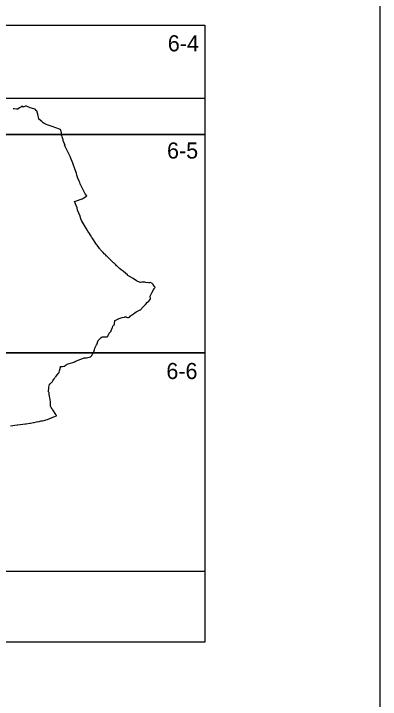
# Model space of a CAD drawing. Extents: x -449577 to -425530, y -1150048 to -1121091.
# Drawn here: x -443133.6 to -442923.9, y -1126663.9 to -1126271.9 of the extents above; entities that cross this region are included whole.
import ezdxf

# ---------------------------------------------------------------- set-up
doc = ezdxf.new("R2010")
doc.units = 0
for name, color, linetype in [('Vrstva 1', 7, 'Continuous'), ('Vrstva 10', 7, 'Continuous'), ('Vrstva 4', 7, 'Continuous')]:
    doc.layers.add(name, color=color, linetype=linetype)

msp = doc.modelspace()

# ---------------------------------------------------------------- linework, layer by layer
at = {"layer": 'Vrstva 1'}
msp.add_lwpolyline([(-444408.89, -1126016.81), (-444408.89, -1127066.81), (-442923.89, -1127066.81), (-442923.89, -1126016.81)], close=True, dxfattribs=at)
msp.add_lwpolyline([(-443135.43, -1126507.56), (-443131.56, -1126506.99), (-443131.32, -1126506.96), (-443127.02, -1126506.44), (-443126.49, -1126506.38), (-443124.34, -1126506.02), (-443124.02, -1126505.97), (-443122.36, -1126505.7), (-443121.96, -1126505.63), (-443120.55, -1126505.34), (-443119.26, -1126505.07), (-443119.05, -1126505.03), (-443117.88, -1126504.8), (-443117.21, -1126504.67), (-443117.19, -1126504.67), (-443116.28, -1126504.46), (-443116.21, -1126504.44), (-443115.56, -1126504.28), (-443115.21, -1126504.17), (-443114.32, -1126503.88), (-443113.88, -1126503.73), (-443113.23, -1126503.49), (-443113.11, -1126503.45), (-443112.02, -1126502.96), (-443112.02, -1126502.96), (-443111.9, -1126502.92), (-443111.25, -1126502.69), (-443111.16, -1126502.66), (-443110.73, -1126502.5), (-443109.07, -1126501.92), (-443109.09, -1126501.87), (-443109.2, -1126501.7), (-443109.36, -1126501.47), (-443109.58, -1126501.15), (-443111.28, -1126498.51), (-443111.49, -1126498.16), (-443111.66, -1126497.89), (-443112.1, -1126497.18), (-443112.63, -1126496.33), (-443112.47, -1126493.97), (-443112.46, -1126493.88), (-443112.85, -1126491.58), (-443112.85, -1126491.56), (-443112.86, -1126491.54), (-443112.86, -1126491.54), (-443112.86, -1126491.51), (-443113.27, -1126489.68), (-443113.28, -1126489.49), (-443113.34, -1126488.69), (-443113.44, -1126488.41), (-443113.45, -1126488.39), (-443113.56, -1126488.17), (-443113.6, -1126488.09), (-443113.61, -1126487.71), (-443113.64, -1126487.01), (-443113.59, -1126486.52), (-443113.59, -1126486.5), (-443113.5, -1126485.64), (-443113.48, -1126485.53), (-443113.19, -1126483.89), (-443113.11, -1126483.81), (-443112.81, -1126483.47), (-443112.75, -1126483.4), (-443112.49, -1126483.28), (-443112.43, -1126483.22), (-443112.17, -1126483.02), (-443111.94, -1126482.84), (-443111.73, -1126482.68), (-443111.67, -1126482.64), (-443111.59, -1126482.51), (-443111.51, -1126482.39), (-443111.4, -1126482.22), (-443111.18, -1126481.89), (-443110.76, -1126481.24), (-443110.63, -1126480.99), (-443110.62, -1126480.98), (-443110.48, -1126480.69), (-443110.43, -1126480.6), (-443110.25, -1126480.27), (-443110.11, -1126480.12), (-443109.81, -1126479.81), (-443109.64, -1126479.63), (-443109.36, -1126479.28), (-443109.23, -1126479.11), (-443108.54, -1126478.26), (-443107.88, -1126477.45), (-443107.59, -1126477.09), (-443107.35, -1126475.92), (-443107.29, -1126475.69), (-443107.22, -1126475.41), (-443106.9, -1126474.1), (-443106.82, -1126473.82), (-443106.82, -1126473.79), (-443106.8, -1126473.74), (-443106.64, -1126473.73), (-443106.62, -1126473.73), (-443106.38, -1126473.73), (-443105.69, -1126473.71), (-443105.68, -1126473.71), (-443105.65, -1126473.71), (-443104.97, -1126473.53), (-443104.77, -1126473.47), (-443104.35, -1126473.36), (-443104.33, -1126473.35), (-443104.27, -1126473.29), (-443103.97, -1126473.01), (-443103.85, -1126472.93), (-443103.51, -1126472.67), (-443103.09, -1126472.35), (-443103.02, -1126472.33), (-443102.46, -1126472.17), (-443099.76, -1126471.41), (-443099.17, -1126471.14), (-443098.84, -1126470.98), (-443098.79, -1126470.96), (-443098.69, -1126470.91), (-443098.33, -1126470.73), (-443098.28, -1126470.71), (-443098.25, -1126470.69), (-443098.24, -1126470.69), (-443098.21, -1126470.67), (-443097.9, -1126470.52), (-443097.84, -1126470.48), (-443097.73, -1126470.43), (-443096.65, -1126470.1), (-443096.22, -1126469.92), (-443095.7, -1126469.7), (-443094.69, -1126469.29), (-443093.27, -1126468.66), (-443093.13, -1126468.65), (-443092, -1126468.6), (-443089.6, -1126468.04), (-443089.07, -1126467.64), (-443089, -1126467.52), (-443088.91, -1126467.34), (-443088.65, -1126466.83), (-443088.3, -1126466.4), (-443088.28, -1126466.37), (-443088.07, -1126466.08), (-443087.96, -1126465.92), (-443087.95, -1126465.91), (-443087.41, -1126464.13), (-443087.4, -1126464.1), (-443087.2, -1126463.15), (-443086.94, -1126462.69), (-443086.75, -1126462.36), (-443086.2, -1126461.24), (-443085.82, -1126460.73), (-443085.79, -1126460.6), (-443085.72, -1126460.3), (-443085.69, -1126460.16), (-443085.63, -1126459.91), (-443085.61, -1126459.81), (-443085.29, -1126458.8), (-443085.28, -1126458.79), (-443084.99, -1126458.51), (-443084.33, -1126457.88), (-443084.28, -1126457.83), (-443083.81, -1126457.35), (-443083.55, -1126457.09), (-443083.45, -1126456.98), (-443083.08, -1126456.66), (-443083.04, -1126456.66), (-443083.03, -1126456.66), (-443082.62, -1126456.65), (-443082.45, -1126456.66), (-443081.82, -1126456.68), (-443081.11, -1126456.68), (-443080.14, -1126456.59), (-443080.11, -1126456.59), (-443079.86, -1126456.56), (-443079.64, -1126456.2), (-443079.59, -1126456.07), (-443079.57, -1126456.02), (-443079.55, -1126455.96), (-443079.19, -1126454.94), (-443079.05, -1126454.77), (-443078.95, -1126454.66), (-443078.91, -1126454.62), (-443078.85, -1126454.54), (-443078.73, -1126454.41), (-443078.46, -1126454.09), (-443078.37, -1126453.99), (-443078.27, -1126453.87), (-443077.93, -1126453.48), (-443077.86, -1126453.09), (-443077.8, -1126452.78), (-443077.73, -1126452.65), (-443077.18, -1126451.73), (-443077.07, -1126451.34), (-443076.88, -1126450.64), (-443076.76, -1126450.35), (-443076.47, -1126450.08), (-443075.92, -1126449.57), (-443075.85, -1126449.51), (-443075.75, -1126447.4), (-443074.73, -1126446.91), (-443074.33, -1126446.7), (-443074.08, -1126446.57), (-443073.79, -1126446.41), (-443073.57, -1126446.33), (-443073.23, -1126446.2), (-443073.18, -1126446.19), (-443072.09, -1126445.78), (-443072.08, -1126445.78), (-443071.59, -1126445.72), (-443071.51, -1126445.7), (-443070.48, -1126445.44), (-443070.33, -1126445.4), (-443070.24, -1126445.37), (-443070.07, -1126445.32), (-443069.54, -1126445.15), (-443069.54, -1126445.15), (-443069.53, -1126445.16), (-443069.53, -1126445.16), (-443069.5, -1126445.22), (-443069.37, -1126445.44), (-443068.49, -1126445.54), (-443068.29, -1126445.56), (-443067.93, -1126445.6), (-443067.84, -1126445.56), (-443067.41, -1126445.38), (-443066.76, -1126444.67), (-443065.12, -1126443.51), (-443065.03, -1126443.44), (-443064.86, -1126443.33), (-443064.35, -1126442.91), (-443063.6, -1126442.31), (-443062.33, -1126441.74), (-443061.71, -1126441.47), (-443061.17, -1126441.23), (-443061.11, -1126441.2), (-443059.46, -1126439.53), (-443058.62, -1126438.64), (-443058.26, -1126438.26), (-443057.07, -1126436.9), (-443056.47, -1126436.44), (-443056.42, -1126436.4), (-443055.58, -1126435.39), (-443055.38, -1126434.82), (-443055.47, -1126433.49), (-443055.25, -1126433), (-443054.61, -1126431.55), (-443053.15, -1126429.07), (-443053.12, -1126429.02), (-443053.12, -1126429.02), (-443053.1, -1126428.99), (-443053.07, -1126428.95), (-443052.92, -1126428.76), (-443052.66, -1126428.42), (-443052.92, -1126428.12), (-443053.06, -1126427.9), (-443053.53, -1126427.16), (-443053.73, -1126426.97), (-443053.88, -1126426.81), (-443054.07, -1126426.61), (-443054.65, -1126426.04), (-443055.5, -1126425.57), (-443055.95, -1126425.75), (-443056.28, -1126425.87), (-443058.03, -1126425.6), (-443058.64, -1126425.51), (-443058.78, -1126425.5), (-443059.37, -1126425.48), (-443059.75, -1126425.43), (-443059.91, -1126425.4), (-443059.95, -1126425.4), (-443059.98, -1126425.39), (-443059.98, -1126425.39), (-443060.01, -1126425.4), (-443060.11, -1126425.43), (-443060.24, -1126425.46), (-443061.14, -1126425.7), (-443061.21, -1126425.67), (-443063.28, -1126424.63), (-443065.3, -1126423.35), (-443068.21, -1126421.53), (-443068.37, -1126421.39), (-443068.41, -1126421.36), (-443068.5, -1126421.28), (-443069.64, -1126420.35), (-443070.79, -1126419.3), (-443070.9, -1126419.2), (-443072.11, -1126418.44), (-443072.39, -1126418.21), (-443073.02, -1126417.71), (-443073.33, -1126417.47), (-443073.83, -1126416.94), (-443074.55, -1126416.18), (-443074.7, -1126416.02), (-443075.16, -1126415.53), (-443076.13, -1126414.5), (-443076.33, -1126414.39), (-443076.33, -1126414.39), (-443076.51, -1126414.3), (-443076.71, -1126414.2), (-443077.54, -1126413.37), (-443078.17, -1126412.74), (-443079.35, -1126411.57), (-443080.28, -1126410.63), (-443080.44, -1126410.48), (-443080.88, -1126410.03), (-443081.12, -1126409.79), (-443081.21, -1126409.7), (-443081.25, -1126409.66), (-443081.77, -1126409.14), (-443082.41, -1126408.49), (-443082.49, -1126408.41), (-443082.51, -1126408.39), (-443082.66, -1126408.24), (-443083.49, -1126407.4), (-443083.87, -1126406.9), (-443084.15, -1126406.53), (-443084.47, -1126406.1), (-443084.83, -1126405.62), (-443085.78, -1126404.36), (-443086.15, -1126403.82), (-443088.69, -1126400.08), (-443088.86, -1126399.82), (-443089.63, -1126398.63), (-443090.3, -1126397.62), (-443091.14, -1126396.29), (-443091.94, -1126395.02), (-443092.02, -1126394.89), (-443093.11, -1126393.04), (-443094.79, -1126390.19), (-443094.79, -1126390.18), (-443094.79, -1126390.18), (-443094.8, -1126390.18), (-443095.13, -1126389.2), (-443095.58, -1126387.9), (-443095.64, -1126387.7), (-443097.02, -1126384.19), (-443097.31, -1126382.94), (-443098.79, -1126379.26), (-443098.16, -1126379.06), (-443094.44, -1126377.82), (-443092.47, -1126376.6), (-443092.29, -1126376.49), (-443092.23, -1126376.45), (-443092.03, -1126376.33), (-443091.76, -1126376.16), (-443092.68, -1126374.97), (-443094.09, -1126372.19), (-443094.84, -1126370.72), (-443095.37, -1126369.56), (-443095.39, -1126369.52), (-443095.45, -1126369.39), (-443095.46, -1126369.36), (-443095.48, -1126369.33), (-443095.52, -1126369.24), (-443095.85, -1126368.51), (-443096.17, -1126367.72), (-443096.88, -1126365.95), (-443097.29, -1126364.91), (-443097.44, -1126364.28), (-443097.7, -1126363.15), (-443098.44, -1126361.26), (-443098.64, -1126360.66), (-443099.58, -1126358.03), (-443099.85, -1126357.31), (-443101.04, -1126354.22), (-443101.11, -1126354.04), (-443101.14, -1126353.96), (-443104.49, -1126347.15), (-443104.18, -1126347.01), (-443104.16, -1126347), (-443104.26, -1126346.83), (-443104.34, -1126346.73), (-443104.51, -1126346.5), (-443104.57, -1126346.42), (-443105.18, -1126344.94), (-443105.23, -1126344.65), (-443105.33, -1126344.19), (-443105.34, -1126344.13), (-443105.85, -1126342.29), (-443106.15, -1126341.66), (-443106.16, -1126341.58), (-443106.2, -1126341.22), (-443106.34, -1126340.13), (-443106.62, -1126338.29), (-443106.68, -1126338.27), (-443106.98, -1126338.17), (-443107.36, -1126337.91), (-443107.37, -1126337.91), (-443111.67, -1126336.5), (-443114.46, -1126335.52), (-443115.77, -1126334.9), (-443116.74, -1126334.34), (-443117.46, -1126333.56), (-443119.14, -1126332.29), (-443119.2, -1126331.99), (-443119.78, -1126329.29), (-443119.93, -1126328.75), (-443120.11, -1126328.24), (-443120.16, -1126328.08), (-443120.41, -1126327.56), (-443120.66, -1126327.25), (-443121.24, -1126326.56), (-443121.99, -1126326.35), (-443124.17, -1126325.69), (-443126.26, -1126324.73), (-443126.88, -1126324.73), (-443127.83, -1126325.1), (-443127.96, -1126325.19), (-443128.03, -1126325.24), (-443128.17, -1126325.34), (-443128.21, -1126325.37), (-443128.23, -1126325.35), (-443128.44, -1126325.1), (-443128.69, -1126324.82), (-443128.77, -1126324.72), (-443128.86, -1126324.76), (-443129.37, -1126325.15), (-443129.56, -1126325.3), (-443130.23, -1126325.82), (-443130.98, -1126326.38), (-443131.32, -1126326.6), (-443131.91, -1126326.56), (-443133.39, -1126326.41), (-443133.85, -1126326.32)], dxfattribs=at)
at = {"layer": 'Vrstva 10'}
msp.add_lwpolyline([(-443024.3, -1126320.23), (-443024.3, -1126631.21), (-443357.17, -1126631.21), (-443357.17, -1126465.91), (-443336.8, -1126465.91), (-443336.8, -1126340.91), (-443336.8, -1126320.23), (-443024.3, -1126320.23)], dxfattribs=at)
at = {"layer": 'Vrstva 4'}
msp.add_line((-443336.8, -1126278.41), (-443024.3, -1126278.41), dxfattribs=at)
msp.add_lwpolyline([(-443024.3, -1126278.41), (-443024.3, -1126340.91), (-443180.55, -1126340.91), (-443180.55, -1126278.41)], dxfattribs=at)
for points in [[(-443024.3, -1126340.91), (-443024.3, -1126465.91), (-443180.55, -1126465.91), (-443180.55, -1126340.91)], [(-443024.3, -1126465.91), (-443024.3, -1126590.91), (-443180.55, -1126590.91), (-443180.55, -1126465.91)]]:
    msp.add_lwpolyline(points, close=True, dxfattribs=at)

# ---------------------------------------------------------------- texts
at = {"layer": 'Vrstva 1'}
for s, p in [('6-4', (-443045.43, -1126293.46)), ('6-5', (-443045.88, -1126354.75)), ('6-6', (-443046.25, -1126480.82))]:
    msp.add_text(s, height=9.2, dxfattribs=at).set_placement(p)

doc.saveas('drawing.dxf')
